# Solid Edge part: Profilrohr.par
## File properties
Username: bmolnar
Dokumentum tartalom típus: 0
Author: bmolnar
Last saved by: bmolnar
Revision: 79
Sűrűség: 0,000 kg/m^3
Pontosság: 0,990
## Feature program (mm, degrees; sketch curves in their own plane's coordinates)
base feature "unnamed BaseFeature 1"
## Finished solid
Body 1: solid body, 95 faces, 278 edges, 184 vertices.
  Faces by surface: plane 48, cylinder 47
  Edges by curve: line 184, circle 94
Bounding box of the edges (mm): 65.500 x 65.500 x 31.000, from (-32.75, -32.75, 0) to (32.75, 32.75, 31).
Cylindrical faces by radius (mm): R0.15 x20, R0.25 x20, R6.5 x2, R8 x4, R25 x1
Planar faces by outward normal: +x 11, +y 12, +z 1, -x 11, -y 12, -z 1
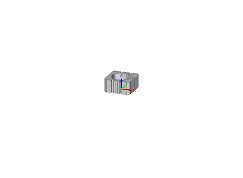
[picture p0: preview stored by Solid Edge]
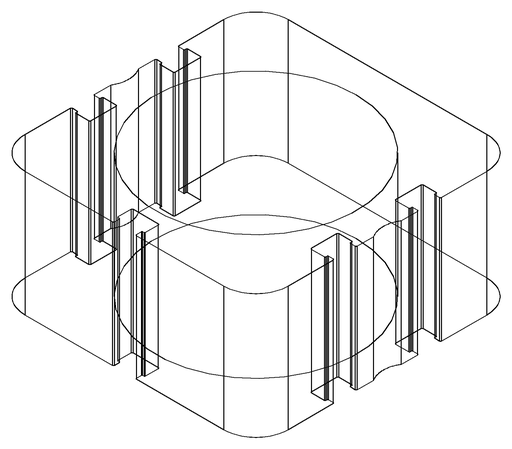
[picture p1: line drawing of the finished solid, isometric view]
